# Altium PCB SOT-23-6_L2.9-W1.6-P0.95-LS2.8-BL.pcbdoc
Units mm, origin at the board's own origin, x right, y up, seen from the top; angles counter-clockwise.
Board outline 16.06 x 16.17 mm, 2 copper layers (Top Layer, Bottom Layer), stack 0 mm thick; 1 components, 0 nets, 6 pads, 0 vias.
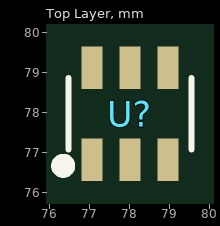
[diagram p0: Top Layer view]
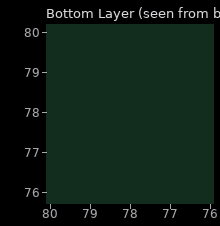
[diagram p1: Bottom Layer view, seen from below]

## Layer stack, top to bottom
Top Layer: signal copper (thickness not stored)
Bottom Layer: signal copper (thickness not stored)

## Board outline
85.908,69.85 69.85,69.85 69.85,86.015 85.908,86.015

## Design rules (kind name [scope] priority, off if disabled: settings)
PasteMaskExpansion "Paste Mask Expansion" [All] p1: expansion=0
SolderMaskExpansion "Solder Mask Expansion" [IsVia] p1: expansion=-25.4 istentingtop=TRUE
SolderMaskExpansion "Solder Mask Expansion" [All] p2: expansion=0.051 istentingtop=FALSE

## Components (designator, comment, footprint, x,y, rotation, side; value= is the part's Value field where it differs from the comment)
U? "" SOT-23-6_L2.9-W1.6-P0.95-LS2.8-BL 78.018,77.98 r0 top

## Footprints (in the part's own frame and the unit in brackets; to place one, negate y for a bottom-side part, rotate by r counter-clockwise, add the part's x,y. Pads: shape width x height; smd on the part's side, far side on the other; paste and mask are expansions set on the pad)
SOT-23-6_L2.9-W1.6-P0.95-LS2.8-BL [mm]
  rect 0.532x1.072 smd: 1(-0.95,-1.149) 2(0,-1.149) 3(0.95,-1.149) 4(0.95,1.149) 5(0,1.149) 6(-0.95,1.149)
  silkscreen extent -1.82,-1.45 1.54,0.89

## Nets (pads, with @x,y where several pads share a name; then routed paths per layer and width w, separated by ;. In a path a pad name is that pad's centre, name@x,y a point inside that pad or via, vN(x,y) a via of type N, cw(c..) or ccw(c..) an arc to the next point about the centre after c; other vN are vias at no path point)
pads on no net: U?.1 U?.2 U?.3 U?.4 U?.5 U?.6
